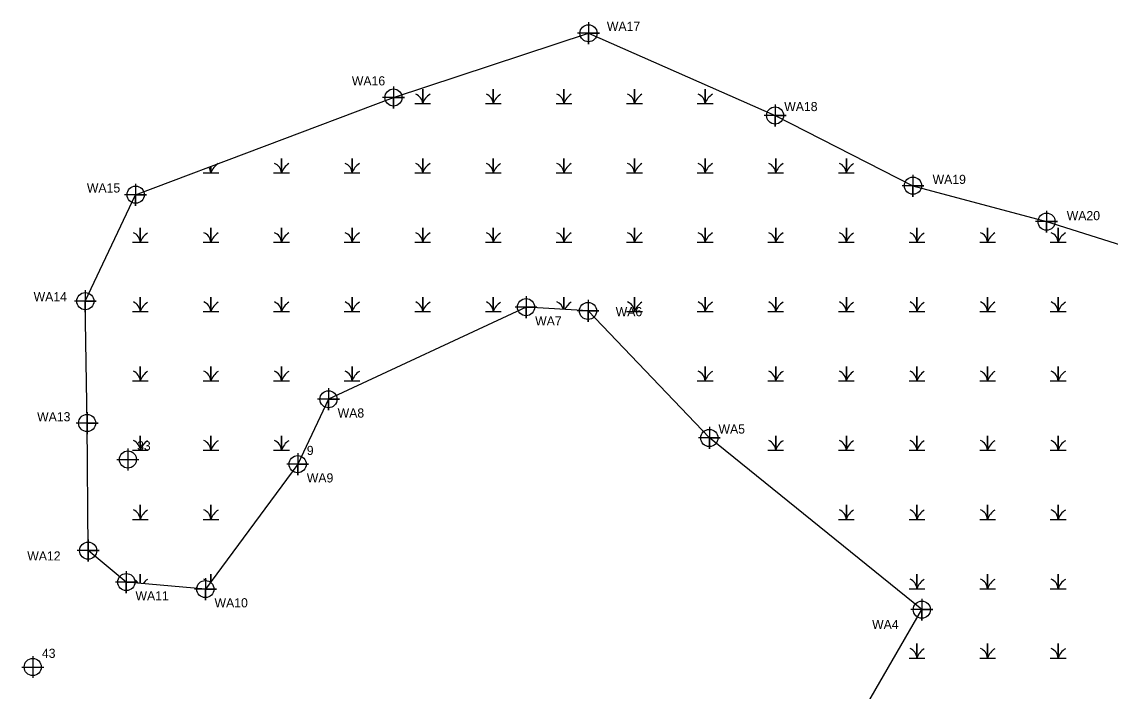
# Model space of a CAD drawing. Extents: x 2603618 to 2605510, y 618189 to 619022.
# Drawn here: x 2603617.8 to 2603915.3, y 618368.6 to 618551.7 of the extents above; entities that cross this region are included whole.
import ezdxf

# ---------------------------------------------------------------- set-up
doc = ezdxf.new("R2010")
doc.units = 0
for name, color, linetype in [('Cogo Default Point CELL', 7, 'Continuous'), ('COGO Default Point Number', 7, 'Continuous'), ('Exist Environmental Wetland Boundary', 7, 'Continuous'), ('Exist Environmental Wetland Boundary Cogo Comment', 7, 'Continuous'), ('Exist Environmental Wetland Boundary Cogo Number', 7, 'Continuous'), ('Exist Environmental Wetland Boundary Cogo Point CELL', 7, 'Continuous')]:
    doc.layers.add(name, color=color, linetype=linetype)

msp = doc.modelspace()

# ---------------------------------------------------------------- linework, layer by layer
at = {"layer": 'Cogo Default Point CELL'}
for points in [[(2603646.79, 618434.99), (2603646.79, 618431.99)], [(2603643.79, 618431.99), (2603646.79, 618431.99)], [(2603646.79, 618431.99), (2603649.79, 618431.99)], [(2603646.79, 618431.99), (2603646.79, 618428.99)], [(2603620.77, 618378.25), (2603620.77, 618375.25)], [(2603617.77, 618375.25), (2603620.77, 618375.25)], [(2603620.77, 618375.25), (2603623.77, 618375.25)], [(2603620.77, 618375.25), (2603620.77, 618372.25)]]:
    msp.add_lwpolyline(points, dxfattribs=at)
for centre in [(2603646.79, 618431.99), (2603620.77, 618375.25)]:
    msp.add_circle(centre, 2.34, dxfattribs=at)
at = {"layer": 'Exist Environmental Wetland Boundary'}
for points in [[(2603758.52, 618194.26), (2603782.96, 618259.35), (2603822.24, 618319.06), (2603863.83, 618390.93), (2603805.73, 618437.87), (2603772.56, 618472.6), (2603755.61, 618473.62), (2603701.62, 618448.45), (2603693.19, 618430.71), (2603667.96, 618396.56), (2603646.35, 618398.47), (2603635.91, 618407.07), (2603635.63, 618441.95), (2603635.14, 618475.26), (2603648.89, 618504.38), (2603719.39, 618530.95), (2603772.69, 618548.52), (2603823.7, 618526.04), (2603861.4, 618506.84), (2603897.92, 618497.01), (2603938.9, 618484.11)], [(2603725.22, 618529.27), (2603727.37, 618529.27), (2603727.37, 618533.22), (2603727.37, 618529.27), (2603729.52, 618529.27)], [(2603744.52, 618529.27), (2603746.67, 618529.27), (2603746.67, 618533.22), (2603746.67, 618529.27), (2603748.82, 618529.27)], [(2603763.82, 618529.27), (2603765.97, 618529.27), (2603765.97, 618533.22), (2603765.97, 618529.27), (2603768.12, 618529.27)], [(2603783.12, 618529.27), (2603785.28, 618529.27), (2603785.28, 618533.22), (2603785.28, 618529.27), (2603787.43, 618529.27)], [(2603802.43, 618529.27), (2603804.58, 618529.27), (2603804.58, 618533.22), (2603804.58, 618529.27), (2603806.73, 618529.27)], [(2603686.62, 618510.33), (2603688.77, 618510.33), (2603688.77, 618514.27), (2603688.77, 618510.33), (2603690.92, 618510.33)], [(2603705.92, 618510.33), (2603708.07, 618510.33), (2603708.07, 618514.27), (2603708.07, 618510.33), (2603710.22, 618510.33)], [(2603725.22, 618510.33), (2603727.37, 618510.33), (2603727.37, 618514.27), (2603727.37, 618510.33), (2603729.52, 618510.33)], [(2603744.52, 618510.33), (2603746.67, 618510.33), (2603746.67, 618514.27), (2603746.67, 618510.33), (2603748.82, 618510.33)], [(2603763.82, 618510.33), (2603765.97, 618510.33), (2603765.97, 618514.27), (2603765.97, 618510.33), (2603768.12, 618510.33)], [(2603783.12, 618510.33), (2603785.28, 618510.33), (2603785.28, 618514.27), (2603785.28, 618510.33), (2603787.43, 618510.33)], [(2603802.43, 618510.33), (2603804.58, 618510.33), (2603804.58, 618514.27), (2603804.58, 618510.33), (2603806.73, 618510.33)], [(2603821.73, 618510.33), (2603823.88, 618510.33), (2603823.88, 618514.27), (2603823.88, 618510.33), (2603826.03, 618510.33)], [(2603841.03, 618510.33), (2603843.18, 618510.33), (2603843.18, 618514.27), (2603843.18, 618510.33), (2603845.33, 618510.33)], [(2603667.32, 618510.33), (2603669.47, 618510.33), (2603669.47, 618512.14)], [(2603669.47, 618512.14), (2603669.47, 618510.33), (2603671.62, 618510.33)], [(2603648.02, 618491.38), (2603650.17, 618491.38), (2603650.17, 618495.33), (2603650.17, 618491.38), (2603652.32, 618491.38)], [(2603667.32, 618491.38), (2603669.47, 618491.38), (2603669.47, 618495.33), (2603669.47, 618491.38), (2603671.62, 618491.38)], [(2603686.62, 618491.38), (2603688.77, 618491.38), (2603688.77, 618495.33), (2603688.77, 618491.38), (2603690.92, 618491.38)], [(2603705.92, 618491.38), (2603708.07, 618491.38), (2603708.07, 618495.33), (2603708.07, 618491.38), (2603710.22, 618491.38)], [(2603725.22, 618491.38), (2603727.37, 618491.38), (2603727.37, 618495.33), (2603727.37, 618491.38), (2603729.52, 618491.38)], [(2603744.52, 618491.38), (2603746.67, 618491.38), (2603746.67, 618495.33), (2603746.67, 618491.38), (2603748.82, 618491.38)], [(2603763.82, 618491.38), (2603765.97, 618491.38), (2603765.97, 618495.33), (2603765.97, 618491.38), (2603768.12, 618491.38)], [(2603783.12, 618491.38), (2603785.28, 618491.38), (2603785.28, 618495.33), (2603785.28, 618491.38), (2603787.43, 618491.38)], [(2603802.43, 618491.38), (2603804.58, 618491.38), (2603804.58, 618495.33), (2603804.58, 618491.38), (2603806.73, 618491.38)], [(2603821.73, 618491.38), (2603823.88, 618491.38), (2603823.88, 618495.33), (2603823.88, 618491.38), (2603826.03, 618491.38)], [(2603841.03, 618491.38), (2603843.18, 618491.38), (2603843.18, 618495.33), (2603843.18, 618491.38), (2603845.33, 618491.38)], [(2603860.33, 618491.38), (2603862.48, 618491.38), (2603862.48, 618495.33), (2603862.48, 618491.38), (2603864.63, 618491.38)], [(2603879.63, 618491.38), (2603881.78, 618491.38), (2603881.78, 618495.33), (2603881.78, 618491.38), (2603883.93, 618491.38)], [(2603898.93, 618491.38), (2603901.08, 618491.38), (2603901.08, 618495.33), (2603901.08, 618491.38), (2603903.23, 618491.38)], [(2603648.02, 618472.44), (2603650.17, 618472.44), (2603650.17, 618476.38), (2603650.17, 618472.44), (2603652.32, 618472.44)], [(2603667.32, 618472.44), (2603669.47, 618472.44), (2603669.47, 618476.38), (2603669.47, 618472.44), (2603671.62, 618472.44)], [(2603686.62, 618472.44), (2603688.77, 618472.44), (2603688.77, 618476.38), (2603688.77, 618472.44), (2603690.92, 618472.44)], [(2603705.92, 618472.44), (2603708.07, 618472.44), (2603708.07, 618476.38), (2603708.07, 618472.44), (2603710.22, 618472.44)], [(2603725.22, 618472.44), (2603727.37, 618472.44), (2603727.37, 618476.38), (2603727.37, 618472.44), (2603729.52, 618472.44)], [(2603744.52, 618472.44), (2603746.67, 618472.44), (2603746.67, 618476.38), (2603746.67, 618472.44), (2603748.82, 618472.44)], [(2603765.97, 618473), (2603765.97, 618476.38), (2603765.97, 618473)], [(2603783.12, 618472.44), (2603785.28, 618472.44), (2603785.28, 618476.38), (2603785.28, 618472.44), (2603787.43, 618472.44)], [(2603802.43, 618472.44), (2603804.58, 618472.44), (2603804.58, 618476.38), (2603804.58, 618472.44), (2603806.73, 618472.44)], [(2603821.73, 618472.44), (2603823.88, 618472.44), (2603823.88, 618476.38), (2603823.88, 618472.44), (2603826.03, 618472.44)], [(2603841.03, 618472.44), (2603843.18, 618472.44), (2603843.18, 618476.38), (2603843.18, 618472.44), (2603845.33, 618472.44)], [(2603860.33, 618472.44), (2603862.48, 618472.44), (2603862.48, 618476.38), (2603862.48, 618472.44), (2603864.63, 618472.44)], [(2603879.63, 618472.44), (2603881.78, 618472.44), (2603881.78, 618476.38), (2603881.78, 618472.44), (2603883.93, 618472.44)], [(2603898.93, 618472.44), (2603901.08, 618472.44), (2603901.08, 618476.38), (2603901.08, 618472.44), (2603903.23, 618472.44)], [(2603648.02, 618453.49), (2603650.17, 618453.49), (2603650.17, 618457.44), (2603650.17, 618453.49), (2603652.32, 618453.49)], [(2603667.32, 618453.49), (2603669.47, 618453.49), (2603669.47, 618457.44), (2603669.47, 618453.49), (2603671.62, 618453.49)], [(2603686.62, 618453.49), (2603688.77, 618453.49), (2603688.77, 618457.44), (2603688.77, 618453.49), (2603690.92, 618453.49)], [(2603705.92, 618453.49), (2603708.07, 618453.49), (2603708.07, 618457.44), (2603708.07, 618453.49), (2603710.22, 618453.49)], [(2603802.43, 618453.49), (2603804.58, 618453.49), (2603804.58, 618457.44), (2603804.58, 618453.49), (2603806.73, 618453.49)], [(2603821.73, 618453.49), (2603823.88, 618453.49), (2603823.88, 618457.44), (2603823.88, 618453.49), (2603826.03, 618453.49)], [(2603841.03, 618453.49), (2603843.18, 618453.49), (2603843.18, 618457.44), (2603843.18, 618453.49), (2603845.33, 618453.49)], [(2603860.33, 618453.49), (2603862.48, 618453.49), (2603862.48, 618457.44), (2603862.48, 618453.49), (2603864.63, 618453.49)], [(2603879.63, 618453.49), (2603881.78, 618453.49), (2603881.78, 618457.44), (2603881.78, 618453.49), (2603883.93, 618453.49)], [(2603898.93, 618453.49), (2603901.08, 618453.49), (2603901.08, 618457.44), (2603901.08, 618453.49), (2603903.23, 618453.49)], [(2603648.02, 618434.55), (2603650.17, 618434.55), (2603650.17, 618438.49), (2603650.17, 618434.55), (2603652.32, 618434.55)], [(2603667.32, 618434.55), (2603669.47, 618434.55), (2603669.47, 618438.49), (2603669.47, 618434.55), (2603671.62, 618434.55)], [(2603686.62, 618434.55), (2603688.77, 618434.55), (2603688.77, 618438.49), (2603688.77, 618434.55), (2603690.92, 618434.55)], [(2603821.73, 618434.55), (2603823.88, 618434.55), (2603823.88, 618438.49), (2603823.88, 618434.55), (2603826.03, 618434.55)], [(2603841.03, 618434.55), (2603843.18, 618434.55), (2603843.18, 618438.49), (2603843.18, 618434.55), (2603845.33, 618434.55)], [(2603860.33, 618434.55), (2603862.48, 618434.55), (2603862.48, 618438.49), (2603862.48, 618434.55), (2603864.63, 618434.55)], [(2603879.63, 618434.55), (2603881.78, 618434.55), (2603881.78, 618438.49), (2603881.78, 618434.55), (2603883.93, 618434.55)], [(2603898.93, 618434.55), (2603901.08, 618434.55), (2603901.08, 618438.49), (2603901.08, 618434.55), (2603903.23, 618434.55)], [(2603648.02, 618415.6), (2603650.17, 618415.6), (2603650.17, 618419.55), (2603650.17, 618415.6), (2603652.32, 618415.6)], [(2603667.32, 618415.6), (2603669.47, 618415.6), (2603669.47, 618419.55), (2603669.47, 618415.6), (2603671.62, 618415.6)], [(2603841.03, 618415.6), (2603843.18, 618415.6), (2603843.18, 618419.55), (2603843.18, 618415.6), (2603845.33, 618415.6)], [(2603860.33, 618415.6), (2603862.48, 618415.6), (2603862.48, 618419.55), (2603862.48, 618415.6), (2603864.63, 618415.6)], [(2603879.63, 618415.6), (2603881.78, 618415.6), (2603881.78, 618419.55), (2603881.78, 618415.6), (2603883.93, 618415.6)], [(2603898.93, 618415.6), (2603901.08, 618415.6), (2603901.08, 618419.55), (2603901.08, 618415.6), (2603903.23, 618415.6)], [(2603650.17, 618398.13), (2603650.17, 618400.6), (2603650.17, 618398.13)], [(2603669.47, 618398.61), (2603669.47, 618400.6), (2603669.47, 618398.61)], [(2603860.33, 618396.66), (2603862.48, 618396.66), (2603862.48, 618400.6), (2603862.48, 618396.66), (2603864.63, 618396.66)], [(2603879.63, 618396.66), (2603881.78, 618396.66), (2603881.78, 618400.6), (2603881.78, 618396.66), (2603883.93, 618396.66)], [(2603898.93, 618396.66), (2603901.08, 618396.66), (2603901.08, 618400.6), (2603901.08, 618396.66), (2603903.23, 618396.66)], [(2603860.33, 618377.71), (2603862.48, 618377.71), (2603862.48, 618381.66), (2603862.48, 618377.71), (2603864.63, 618377.71)], [(2603879.63, 618377.71), (2603881.78, 618377.71), (2603881.78, 618381.66), (2603881.78, 618377.71), (2603883.93, 618377.71)], [(2603898.93, 618377.71), (2603901.08, 618377.71), (2603901.08, 618381.66), (2603901.08, 618377.71), (2603903.23, 618377.71)]]:
    msp.add_lwpolyline(points, dxfattribs=at)
for centre, radius, start, end in [((2603724.31, 618529.05), 3.07, 4.1403, 67.535), ((2603731.93, 618527.76), 4.81, 122.1274, 161.6222), ((2603743.61, 618529.05), 3.07, 4.1403, 67.535), ((2603751.23, 618527.76), 4.81, 122.1274, 161.6222), ((2603762.91, 618529.05), 3.07, 4.1403, 67.535), ((2603770.53, 618527.76), 4.81, 122.1274, 161.6222), ((2603782.21, 618529.05), 3.07, 4.1403, 67.535), ((2603789.84, 618527.76), 4.81, 122.1274, 161.6222), ((2603801.51, 618529.05), 3.07, 4.1403, 67.535), ((2603809.14, 618527.76), 4.81, 122.1274, 161.6222), ((2603666.4, 618510.1), 3.07, 4.1403, 36.1315), ((2603674.03, 618508.81), 4.81, 122.1274, 161.6222), ((2603685.7, 618510.1), 3.07, 4.1403, 67.535), ((2603693.33, 618508.81), 4.81, 122.1274, 161.6222), ((2603705.01, 618510.1), 3.07, 4.1403, 67.535), ((2603712.63, 618508.81), 4.81, 122.1274, 161.6222), ((2603724.31, 618510.1), 3.07, 4.1403, 67.535), ((2603731.93, 618508.81), 4.81, 122.1274, 161.6222), ((2603743.61, 618510.1), 3.07, 4.1403, 67.535), ((2603751.23, 618508.81), 4.81, 122.1274, 161.6222), ((2603762.91, 618510.1), 3.07, 4.1403, 67.535), ((2603770.53, 618508.81), 4.81, 122.1274, 161.6222), ((2603782.21, 618510.1), 3.07, 4.1403, 67.535), ((2603789.84, 618508.81), 4.81, 122.1274, 161.6222), ((2603801.51, 618510.1), 3.07, 4.1403, 67.535), ((2603809.14, 618508.81), 4.81, 122.1274, 161.6222), ((2603820.81, 618510.1), 3.07, 4.1403, 67.535), ((2603828.44, 618508.81), 4.81, 122.1274, 161.6222), ((2603840.11, 618510.1), 3.07, 4.1403, 67.535), ((2603847.74, 618508.81), 4.81, 122.1274, 161.6222), ((2603647.1, 618491.16), 3.07, 4.1403, 67.535), ((2603654.73, 618489.87), 4.81, 122.1274, 161.6222), ((2603666.4, 618491.16), 3.07, 4.1403, 67.535), ((2603674.03, 618489.87), 4.81, 122.1274, 161.6222), ((2603685.7, 618491.16), 3.07, 4.1403, 67.535), ((2603693.33, 618489.87), 4.81, 122.1274, 161.6222), ((2603705.01, 618491.16), 3.07, 4.1403, 67.535), ((2603712.63, 618489.87), 4.81, 122.1274, 161.6222), ((2603724.31, 618491.16), 3.07, 4.1403, 67.535), ((2603731.93, 618489.87), 4.81, 122.1274, 161.6222), ((2603743.61, 618491.16), 3.07, 4.1403, 67.535), ((2603751.23, 618489.87), 4.81, 122.1274, 161.6222), ((2603762.91, 618491.16), 3.07, 4.1403, 67.535), ((2603770.53, 618489.87), 4.81, 122.1274, 161.6222), ((2603782.21, 618491.16), 3.07, 4.1403, 67.535), ((2603789.84, 618489.87), 4.81, 122.1274, 161.6222), ((2603801.51, 618491.16), 3.07, 4.1403, 67.535), ((2603809.14, 618489.87), 4.81, 122.1274, 161.6222), ((2603820.81, 618491.16), 3.07, 4.1403, 67.535), ((2603828.44, 618489.87), 4.81, 122.1274, 161.6222), ((2603840.11, 618491.16), 3.07, 4.1403, 67.535), ((2603847.74, 618489.87), 4.81, 122.1274, 161.6222), ((2603859.41, 618491.16), 3.07, 4.1403, 67.535), ((2603867.04, 618489.87), 4.81, 122.1274, 161.6222), ((2603878.71, 618491.16), 3.07, 4.1403, 67.535), ((2603886.34, 618489.87), 4.81, 122.1274, 161.6222), ((2603898.01, 618491.16), 3.07, 4.1403, 67.535), ((2603905.64, 618489.87), 4.81, 122.1274, 161.6222), ((2603647.1, 618472.21), 3.07, 4.1403, 67.535), ((2603654.73, 618470.92), 4.81, 122.1274, 161.6222), ((2603666.4, 618472.21), 3.07, 4.1403, 67.535), ((2603674.03, 618470.92), 4.81, 122.1274, 161.6222), ((2603685.7, 618472.21), 3.07, 4.1403, 67.535), ((2603693.33, 618470.92), 4.81, 122.1274, 161.6222), ((2603705.01, 618472.21), 3.07, 4.1403, 67.535), ((2603712.63, 618470.92), 4.81, 122.1274, 161.6222), ((2603724.31, 618472.21), 3.07, 4.1403, 67.535), ((2603731.93, 618470.92), 4.81, 122.1274, 161.6222), ((2603743.61, 618472.21), 3.07, 4.1403, 67.535), ((2603751.23, 618470.92), 4.81, 122.1274, 161.6222), ((2603762.91, 618472.21), 3.07, 14.8324, 67.535), ((2603770.53, 618470.92), 4.81, 122.1274, 154.601), ((2603782.21, 618472.21), 3.07, 4.1403, 67.535), ((2603789.84, 618470.92), 4.81, 122.1274, 161.6222), ((2603801.51, 618472.21), 3.07, 4.1403, 67.535), ((2603809.14, 618470.92), 4.81, 122.1274, 161.6222), ((2603820.81, 618472.21), 3.07, 4.1403, 67.535), ((2603828.44, 618470.92), 4.81, 122.1274, 161.6222), ((2603840.11, 618472.21), 3.07, 4.1403, 67.535), ((2603847.74, 618470.92), 4.81, 122.1274, 161.6222), ((2603859.41, 618472.21), 3.07, 4.1403, 67.535), ((2603867.04, 618470.92), 4.81, 122.1274, 161.6222), ((2603878.71, 618472.21), 3.07, 4.1403, 67.535), ((2603886.34, 618470.92), 4.81, 122.1274, 161.6222), ((2603898.01, 618472.21), 3.07, 4.1403, 67.535), ((2603905.64, 618470.92), 4.81, 122.1274, 161.6222), ((2603647.1, 618453.27), 3.07, 4.1403, 67.535), ((2603654.73, 618451.98), 4.81, 122.1274, 161.6222), ((2603666.4, 618453.27), 3.07, 4.1403, 67.535), ((2603674.03, 618451.98), 4.81, 122.1274, 161.6222), ((2603685.7, 618453.27), 3.07, 4.1403, 67.535), ((2603693.33, 618451.98), 4.81, 122.1274, 161.6222), ((2603705.01, 618453.27), 3.07, 4.1403, 67.535), ((2603712.63, 618451.98), 4.81, 122.1274, 161.6222), ((2603801.51, 618453.27), 3.07, 4.1403, 67.535), ((2603809.14, 618451.98), 4.81, 122.1274, 161.6222), ((2603820.81, 618453.27), 3.07, 4.1403, 67.535), ((2603828.44, 618451.98), 4.81, 122.1274, 161.6222), ((2603840.11, 618453.27), 3.07, 4.1403, 67.535), ((2603847.74, 618451.98), 4.81, 122.1274, 161.6222), ((2603859.41, 618453.27), 3.07, 4.1403, 67.535), ((2603867.04, 618451.98), 4.81, 122.1274, 161.6222), ((2603878.71, 618453.27), 3.07, 4.1403, 67.535), ((2603886.34, 618451.98), 4.81, 122.1274, 161.6222), ((2603898.01, 618453.27), 3.07, 4.1403, 67.535), ((2603905.64, 618451.98), 4.81, 122.1274, 161.6222), ((2603647.1, 618434.32), 3.07, 4.1403, 67.535), ((2603654.73, 618433.03), 4.81, 122.1274, 161.6222), ((2603666.4, 618434.32), 3.07, 4.1403, 67.535), ((2603674.03, 618433.03), 4.81, 122.1274, 161.6222), ((2603685.7, 618434.32), 3.07, 4.1403, 67.535), ((2603693.33, 618433.03), 4.81, 122.1274, 161.6222), ((2603820.81, 618434.32), 3.07, 4.1403, 67.535), ((2603828.44, 618433.03), 4.81, 122.1274, 161.6222), ((2603840.11, 618434.32), 3.07, 4.1403, 67.535), ((2603847.74, 618433.03), 4.81, 122.1274, 161.6222), ((2603859.41, 618434.32), 3.07, 4.1403, 67.535), ((2603867.04, 618433.03), 4.81, 122.1274, 161.6222), ((2603878.71, 618434.32), 3.07, 4.1403, 67.535), ((2603886.34, 618433.03), 4.81, 122.1274, 161.6222), ((2603898.01, 618434.32), 3.07, 4.1403, 67.535), ((2603905.64, 618433.03), 4.81, 122.1274, 161.6222), ((2603647.1, 618415.38), 3.07, 4.1403, 67.535), ((2603654.73, 618414.09), 4.81, 122.1274, 161.6222), ((2603666.4, 618415.38), 3.07, 4.1403, 67.535), ((2603674.03, 618414.09), 4.81, 122.1274, 161.6222), ((2603840.11, 618415.38), 3.07, 4.1403, 67.535), ((2603847.74, 618414.09), 4.81, 122.1274, 161.6222), ((2603859.41, 618415.38), 3.07, 4.1403, 67.535), ((2603867.04, 618414.09), 4.81, 122.1274, 161.6222), ((2603878.71, 618415.38), 3.07, 4.1403, 67.535), ((2603886.34, 618414.09), 4.81, 122.1274, 161.6222), ((2603898.01, 618415.38), 3.07, 4.1403, 67.535), ((2603905.64, 618414.09), 4.81, 122.1274, 161.6222), ((2603647.1, 618396.43), 3.07, 34.5352, 60.7229), ((2603654.73, 618395.14), 4.81, 122.1274, 142.5358), ((2603666.4, 618396.43), 3.07, 52.748, 67.535), ((2603859.41, 618396.43), 3.07, 4.1403, 67.535), ((2603867.04, 618395.14), 4.81, 122.1274, 161.6222), ((2603878.71, 618396.43), 3.07, 4.1403, 67.535), ((2603886.34, 618395.14), 4.81, 122.1274, 161.6222), ((2603898.01, 618396.43), 3.07, 4.1403, 67.535), ((2603905.64, 618395.14), 4.81, 122.1274, 161.6222), ((2603859.41, 618377.49), 3.07, 4.1403, 67.535), ((2603867.04, 618376.19), 4.81, 122.1274, 161.6222), ((2603878.71, 618377.49), 3.07, 4.1403, 67.535), ((2603886.34, 618376.19), 4.81, 122.1274, 161.6222), ((2603898.01, 618377.49), 3.07, 4.1403, 67.535), ((2603905.64, 618376.19), 4.81, 122.1274, 161.6222)]:
    msp.add_arc(centre, radius, start, end, dxfattribs=at)
at = {"layer": 'Exist Environmental Wetland Boundary Cogo Point CELL'}
for points in [[(2603772.69, 618551.52), (2603772.69, 618545.52), (2603772.69, 618548.52), (2603775.69, 618548.52), (2603769.69, 618548.52)], [(2603719.39, 618533.95), (2603719.39, 618527.95), (2603719.39, 618530.95), (2603722.39, 618530.95), (2603716.39, 618530.95)], [(2603823.7, 618529.04), (2603823.7, 618523.04), (2603823.7, 618526.04), (2603826.7, 618526.04), (2603820.7, 618526.04)], [(2603861.4, 618509.84), (2603861.4, 618503.84), (2603861.4, 618506.84), (2603864.4, 618506.84), (2603858.4, 618506.84)], [(2603648.89, 618507.38), (2603648.89, 618501.38), (2603648.89, 618504.38), (2603651.89, 618504.38), (2603645.89, 618504.38)], [(2603897.92, 618500.01), (2603897.92, 618494.01), (2603897.92, 618497.01), (2603900.92, 618497.01), (2603894.92, 618497.01)], [(2603635.14, 618478.26), (2603635.14, 618472.26), (2603635.14, 618475.26), (2603638.14, 618475.26), (2603632.14, 618475.26)], [(2603755.61, 618476.62), (2603755.61, 618470.62), (2603755.61, 618473.62), (2603758.61, 618473.62), (2603752.61, 618473.62)], [(2603772.56, 618475.6), (2603772.56, 618469.6), (2603772.56, 618472.6), (2603775.56, 618472.6), (2603769.56, 618472.6)], [(2603701.62, 618451.45), (2603701.62, 618445.45), (2603701.62, 618448.45), (2603704.62, 618448.45), (2603698.62, 618448.45)], [(2603635.63, 618444.95), (2603635.63, 618438.95), (2603635.63, 618441.95), (2603638.63, 618441.95), (2603632.63, 618441.95)], [(2603805.73, 618440.87), (2603805.73, 618434.87), (2603805.73, 618437.87), (2603808.73, 618437.87), (2603802.73, 618437.87)], [(2603693.19, 618433.71), (2603693.19, 618427.71), (2603693.19, 618430.71), (2603696.19, 618430.71), (2603690.19, 618430.71)], [(2603635.91, 618410.07), (2603635.91, 618404.07), (2603635.91, 618407.07), (2603638.91, 618407.07), (2603632.91, 618407.07)], [(2603646.35, 618401.47), (2603646.35, 618395.47), (2603646.35, 618398.47), (2603649.35, 618398.47), (2603643.35, 618398.47)], [(2603667.96, 618399.56), (2603667.96, 618393.56), (2603667.96, 618396.56), (2603670.96, 618396.56), (2603664.96, 618396.56)], [(2603863.83, 618393.93), (2603863.83, 618387.93), (2603863.83, 618390.93), (2603866.83, 618390.93), (2603860.83, 618390.93)]]:
    msp.add_lwpolyline(points, dxfattribs=at)
for centre in [(2603772.69, 618548.52), (2603719.39, 618530.95), (2603823.7, 618526.04), (2603861.4, 618506.84), (2603648.89, 618504.38), (2603897.92, 618497.01), (2603635.14, 618475.26), (2603755.61, 618473.62), (2603772.56, 618472.6), (2603701.62, 618448.45), (2603635.63, 618441.95), (2603805.73, 618437.87), (2603693.19, 618430.71), (2603635.91, 618407.07), (2603646.35, 618398.47), (2603667.96, 618396.56), (2603863.83, 618390.93)]:
    msp.add_circle(centre, 2.34, dxfattribs=at)

# ---------------------------------------------------------------- texts
at = {"layer": 'COGO Default Point Number'}
for s, p in [('33', (2603649.29, 618434.49)), ('43', (2603623.27, 618377.75))]:
    msp.add_text(s, height=2.5, dxfattribs=at).set_placement(p)
at = {"layer": 'Exist Environmental Wetland Boundary Cogo Comment'}
for s, p in [('WA17', (2603777.72, 618549.16)), ('WA16', (2603708, 618534.26)), ('WA18', (2603826.2, 618527.23)), ('WA19', (2603866.76, 618507.32)), ('WA15', (2603635.57, 618504.98)), ('WA20', (2603903.43, 618497.41)), ('WA14', (2603621.01, 618475.24)), ('WA6', (2603780.13, 618471.14)), ('WA7', (2603758.11, 618468.62)), ('WA8', (2603704.12, 618443.45)), ('WA13', (2603621.96, 618442.42)), ('WA5', (2603808.23, 618439.06)), ('WA9', (2603695.69, 618425.71)), ('WA12', (2603619.27, 618404.37)), ('WA11', (2603648.85, 618393.47)), ('WA10', (2603670.46, 618391.56)), ('WA4', (2603850.22, 618385.64))]:
    msp.add_text(s, height=2.5, dxfattribs=at).set_placement(p)
at = {"layer": 'Exist Environmental Wetland Boundary Cogo Number'}
msp.add_text('9', height=2.5, dxfattribs=at).set_placement((2603695.69, 618433.21))

doc.saveas('drawing.dxf')
